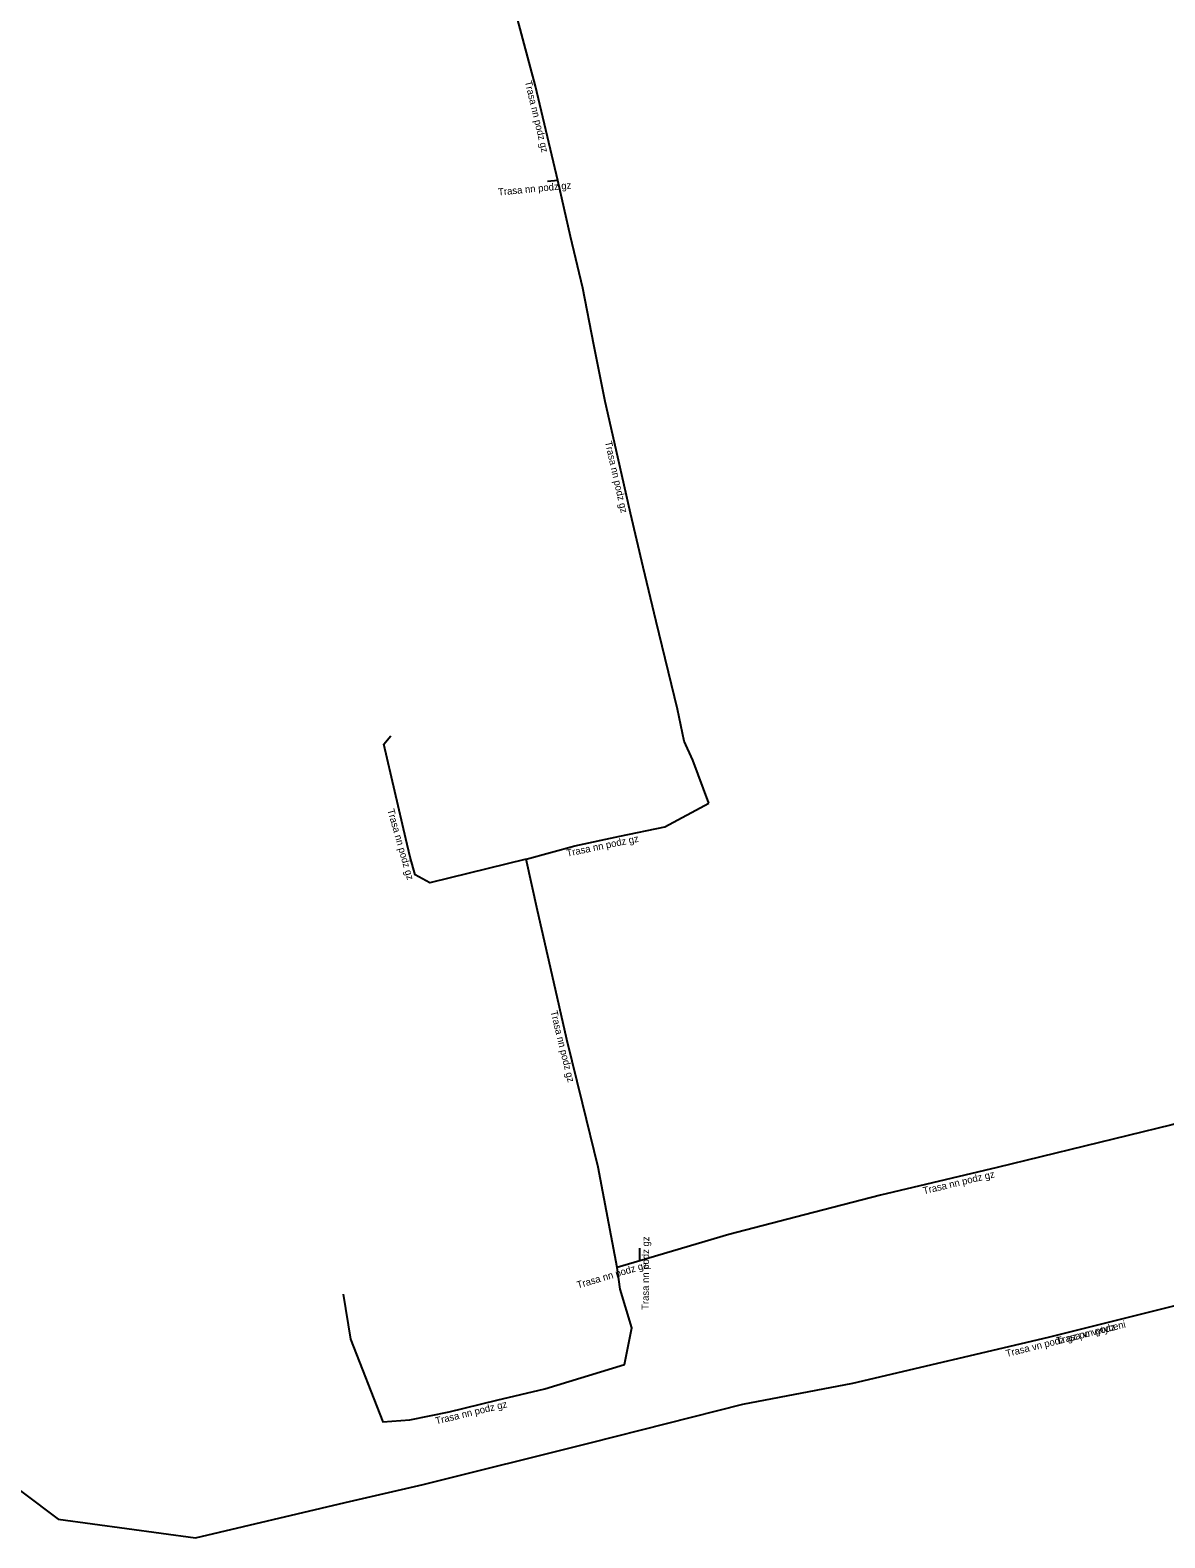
# Model space of a CAD drawing. Extents: x -473162 to -472629, y -1107202 to -1106680.
# Drawn here: x -472873 to -472793.2, y -1107033.1 to -1106927.1 of the extents above; entities that cross this region are included whole.
import ezdxf

# ---------------------------------------------------------------- set-up
doc = ezdxf.new("R2010")
doc.units = 0
for name, color, linetype in [('Popiskový text - Ostatní atributy Trasy', 7, 'Continuous'), ('Spojnice NN', 7, 'Continuous'), ('Spojnice VN', 7, 'Continuous')]:
    doc.layers.add(name, color=color, linetype=linetype)

msp = doc.modelspace()

# ---------------------------------------------------------------- linework, layer by layer
at = {"layer": 'Spojnice NN'}
for points in [[(-472837.43, -1106931), (-472839.75, -1106922.31), (-472842.11, -1106913.36)], [(-472835.85, -1106937.65), (-472837.43, -1106931)], [(-472835.85, -1106937.65), (-472836.58, -1106937.72)], [(-472825.24, -1106981.44), (-472826.36, -1106978.41), (-472826.97, -1106977.07), (-472827.45, -1106974.84), (-472828.94, -1106968.67), (-472829.85, -1106964.85), (-472830.75, -1106961.03), (-472831.64, -1106957.1), (-472832.53, -1106953.18), (-472833.32, -1106949.2), (-472834.1, -1106945.22), (-472834.96, -1106941.57), (-472835.85, -1106937.65)], [(-472838.08, -1106985.37), (-472844.85, -1106987.04), (-472845.88, -1106986.48), (-472846.23, -1106985.25), (-472846.55, -1106983.94), (-472848.08, -1106977.29), (-472847.59, -1106976.71)], [(-472838.08, -1106985.37), (-472834.66, -1106984.44), (-472831.49, -1106983.77), (-472828.33, -1106983.11), (-472825.24, -1106981.44)], [(-472831.68, -1107014.1), (-472833.01, -1107007.04), (-472834.11, -1107002.55), (-472835.22, -1106998.06), (-472836.26, -1106993.52), (-472837.29, -1106988.99), (-472838.08, -1106985.37)], [(-472782.82, -1107001.41), (-472783.23, -1107001.52), (-472787.95, -1107002.79), (-472792.68, -1107004.07), (-472798.83, -1107005.56), (-472804.97, -1107007.06), (-472813.17, -1107009.02), (-472818.5, -1107010.4), (-472823.83, -1107011.78), (-472830.09, -1107013.63)], [(-472830.09, -1107013.63), (-472830.08, -1107012.75)], [(-472850.96, -1107015.98), (-472850.43, -1107019.15), (-472848.17, -1107024.96), (-472846.27, -1107024.82), (-472844.88, -1107024.54), (-472843.5, -1107024.27), (-472840.14, -1107023.45), (-472836.78, -1107022.64), (-472831.17, -1107020.93), (-472830.65, -1107018.36), (-472831.48, -1107015.64), (-472831.68, -1107014.1)], [(-472830.09, -1107013.63), (-472831.68, -1107014.1)]]:
    msp.add_lwpolyline(points, dxfattribs=at)
at = {"layer": 'Spojnice VN'}
msp.add_lwpolyline([(-472875.93, -1107028.1), (-472871, -1107031.82), (-472861.33, -1107033.12), (-472850.8, -1107030.64), (-472845.32, -1107029.36), (-472833.57, -1107026.45), (-472822.85, -1107023.72), (-472815.1, -1107022.25), (-472801.34, -1107019), (-472791.51, -1107016.55), (-472781.55, -1107013.95), (-472772.18, -1107011.27), (-472769.48, -1107010.31), (-472760.41, -1107005.48), (-472750.82, -1106999.47), (-472737.83, -1106992.21), (-472734.32, -1106989.81), (-472728.85, -1106987.34), (-472726.78, -1106986.17), (-472724.29, -1106985.16)], dxfattribs=at)
msp.add_lwpolyline([(-472875.93, -1107028.1), (-472871, -1107031.82), (-472861.33, -1107033.12), (-472850.8, -1107030.64), (-472845.32, -1107029.36), (-472833.57, -1107026.45), (-472822.85, -1107023.72), (-472815.1, -1107022.25), (-472801.34, -1107019), (-472791.51, -1107016.55), (-472781.55, -1107013.95), (-472772.18, -1107011.27), (-472769.48, -1107010.31), (-472760.41, -1107005.48), (-472750.82, -1106999.47), (-472737.83, -1106992.21), (-472734.32, -1106989.81), (-472728.85, -1106987.34), (-472726.78, -1106986.17), (-472724.29, -1106985.16)], dxfattribs=at)

# ---------------------------------------------------------------- texts
at = {"layer": 'Popiskový text - Ostatní atributy Trasy'}
for s, rotation, p in [('Trasa nn podz gz', 283.3898, (-472838.18, -1106930.68)), ('Trasa nn podz gz', 5.4923, (-472840.03, -1106938.7)), ('Trasa nn podz gz', 282.7664, (-472832.55, -1106956.03)), ('Trasa nn podz gz', 285.8839, (-472847.85, -1106981.92)), ('Trasa nn podz gz', 11.8203, (-472835.19, -1106985.21)), ('Trasa nn podz gz', 283.8709, (-472836.38, -1106996.1)), ('Trasa nn podz gz', 13.468, (-472810.12, -1107008.96)), ('Trasa nn podz gz', 89.6569, (-472829.46, -1107017.09)), ('Trasa nn podz gz', 16.4668, (-472834.44, -1107015.59)), ('Trasa vn podz gz po vytyceni', 13.9883, (-472804.29, -1107020.41)), ('Trasa vn podz', 13.9883, (-472800.72, -1107019.52)), ('Trasa nn podz gz', 13.6343, (-472844.4, -1107025.15))]:
    msp.add_text(s, height=0.5, rotation=rotation, dxfattribs=at).set_placement(p)

doc.saveas('drawing.dxf')
